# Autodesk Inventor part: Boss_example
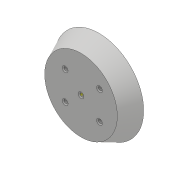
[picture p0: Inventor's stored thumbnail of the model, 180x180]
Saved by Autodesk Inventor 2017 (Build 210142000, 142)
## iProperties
Created: 2016-09
Part Number: Boss_example
Material: Generic
Document SubType Name: Modeling
Designer: Gaurav
Density: 1 g/cm^3
Appearance: Default
Author: Gaurav
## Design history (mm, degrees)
sketch "Sketch1"
  geometry: L1 (0, 0)-(-110, 0); L2 (-110, 0)-(-135.357, 54.378); L3 (-135.357, 54.378)-(0, 54.378); L4 (0, 54.378)-(0, 0)
  constraints: 8 end point, 1 horizontal, 1 parallel, 1 perpendicular
  dimensions: "d0" = 60 distance of L1.end L2.end; "d1" = 115 deg angle of L1 L2
revolve "Revolution1" sketch "Sketch1" stored, may be unused: angle "d2" = 90 deg
shell "Shell1" dims "d3" = 2
workpoint "Work Point1"
sketch "Sketch3"
  geometry: 5 further points
feature "Boss3" sketch "Sketch3" dims "d54" = 3, "d55" = 25, "d56" = 10, "d57" = 8, "d58" = 3, "d59" = 7, "d60" = 2, "d61" = 5, "d62" = 2.5 deg, "d63" = 2.5 deg, "d64" = 2.5 deg, "d65" = 2.5 deg, "d66" = 90 deg, "d69" = 2, "d70" = 2, "d71" = 18, "d72" = 2, "d73" = 10 deg, "d74" = 2.5 deg, "d75" = 0.5, "d76" = 1, "d77" = 0, "d78" = 360 deg
body "Solid1"
